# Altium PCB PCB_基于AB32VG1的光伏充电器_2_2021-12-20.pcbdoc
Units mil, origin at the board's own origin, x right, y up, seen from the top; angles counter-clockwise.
Board outline 4460 x 3310 mil, 2 copper layers (Top Layer, Bottom Layer); 86 components, 49 nets, 230 pads, 42 vias.
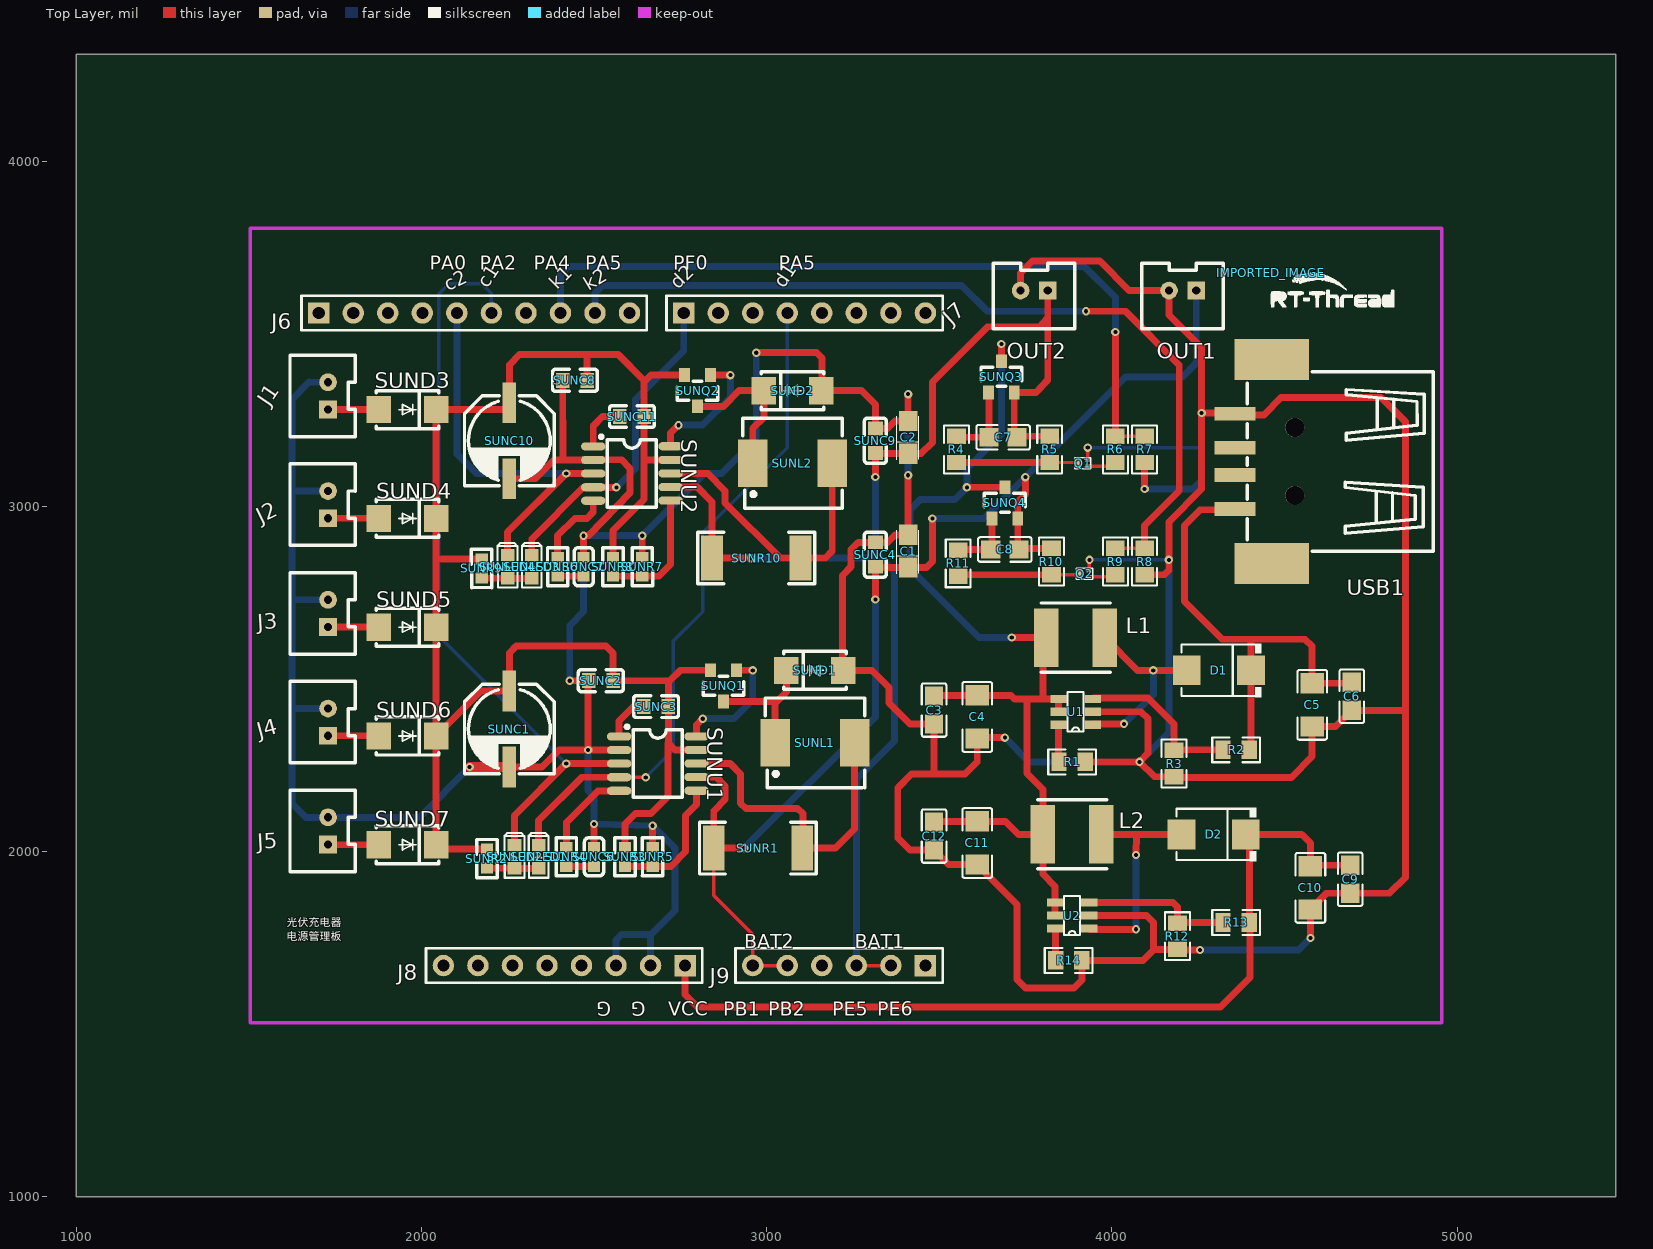
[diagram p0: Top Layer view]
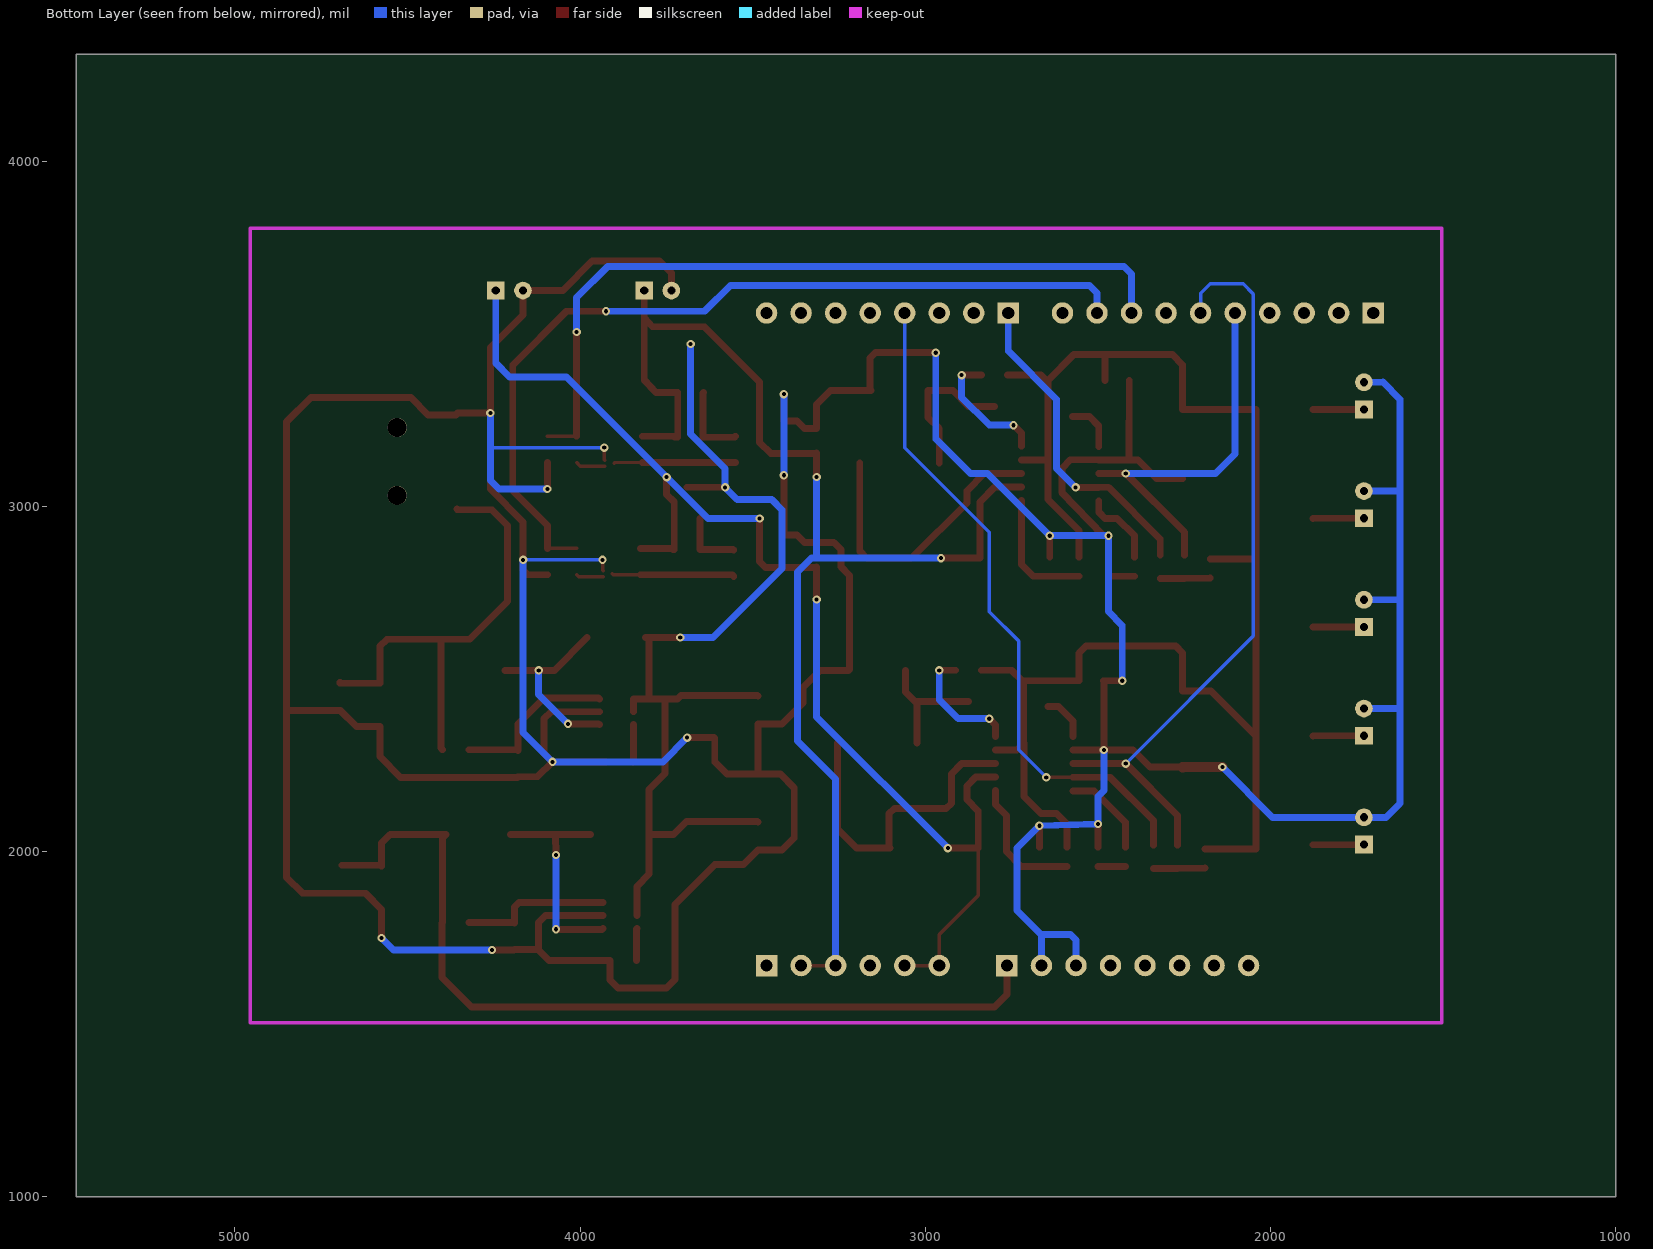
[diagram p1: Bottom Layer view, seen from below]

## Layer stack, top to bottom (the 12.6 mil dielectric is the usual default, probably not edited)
Top Layer: signal copper (thickness not stored)
Dielectric: dielectric 12.6, FR-4, Dk 4.8
Bottom Layer: signal copper (thickness not stored)

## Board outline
5460,1000 1000,1000 1000,4310 5460,4310

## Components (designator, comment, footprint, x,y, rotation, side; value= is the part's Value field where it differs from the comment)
C1 "10u" CASE-A_3216 3410,2870 r90 top
C2 "10u" CASE-A_3216 3410,3200 r90 top
C3 "0.1u" C0805 3485,2410 r90 top
C4 "22u" C1206 3610,2390 r90 top
C5 "22u" C1206 4580,2425 r90 top
C6 "0.1u" C0805 4695,2450 r90 top
C7 "0.1u" C0805 3685,3200 r180 top
C8 "0.1u" C0805 3690,2875 r180 top
C9 "0.1u" C0805 4690,1920 r90 top
C10 "22u" C1206 4575,1895 r90 top
C11 "22u" C1206 3610,2025 r90 top
C12 "0.1u" C0805 3485,2045 r90 top
D1 "SS34BG" SMB_L4.6-W3.6-LS5.3-RD 4310,2525 r180 top
D2 "SS34BG" SMB_L4.6-W3.6-LS5.3-RD 4295,2050 r180 top
IMPORTED_IMAGE "IMPORTED_IMAGE" IMPORTED_IMAGE 4460.66,3675.85 r0 top
J1 "XH2.0-2" XH2.0-2P 1730,3320 r180 top
J2 "XH2.0-2" XH2.0-2P 1730,3005 r180 top
J3 "XH2.0-2" XH2.0-2P 1730,2690 r180 top
J4 "XH2.0-2" XH2.0-2P 1730,2375 r180 top
J5 "XH2.0-2" XH2.0-2P 1730,2060 r180 top
J6 "HDR-M-2.54_1x10" HDR-M-2.54_1X10 2153,3560 r0 top
J7 "HDR-M-2.54_1x8" HDR-M-2.54_1X8 3160,3560 r0 top
J8 "HDR-M-2.54_1x8" HDR-M-2.54_1X8 2364,1670 r180 top
J9 "HDR-M-2.54_1x6" HDR-M-2.54_1X6 3210,1670 r180 top
L1 "3.3uH" IND-SMD_L5.0-W5.0_LQH55DN 3895,2620 r0 top
L2 "3.3uH" IND-SMD_L5.0-W5.0_LQH55DN 3885,2050 r0 top
OUT1 "XH2.0-2" XH2.0-2P 4205,3625 r270 top
OUT2 "XH2.0-2" XH2.0-2P 3775,3625 r270 top
Q1 "MMBT3904FN3" DFN-3L_L1.0-W0.6-P0.65-BR 3915,3125 r0 top
Q2 "MMBT3904FN3" DFN-3L_L1.0-W0.6-P0.65-BR 3920,2805 r0 top
R1 "47k" R0805 3885,2260 r180 top
R2 "88k" R0805 4360,2295 r0 top
R3 "12k" R0805 4180,2255 r90 top
R4 "100k" R0805 3550,3165 r90 top
R5 "10k" R0805 3820,3165 r90 top
R6 "10k" R0805 4010,3165 r270 top
R7 "100k" R0805 4095,3165 r90 top
R8 "100k" R0805 4095,2840 r90 top
R9 "10k" R0805 4010,2840 r270 top
R10 "10k" R0805 3825,2840 r90 top
R11 "100k" R0805 3555,2835 r90 top
R12 "12k" R0805 4190,1755 r90 top
R13 "88k" R0805 4360,1795 r0 top
R14 "47k" R0805 3875,1685 r180 top
SUNC1 "220uF" CAP-SMD_BD6.3-L6.6-W6.6-FD 2255,2355 r270 top
SUNC2 "0.1u" C0603#1 2520,2495 r0 top
SUNC3 "0.1u" C0603#1 2680,2420 r0 top
SUNC4 "0.1u" C0603#1 3315,2860 r270 top
SUNC6 "0.22uF" C0603#2 2500,1985 r270 top
SUNC7 "0.22uF" C0603#2 2470,2825 r270 top
SUNC8 "0.1u" C0603#1 2445,3365 r0 top
SUNC9 "0.1u" C0603#1 3315,3190 r270 top
SUNC10 "220uF" CAP-SMD_BD6.3-L6.6-W6.6-FD 2255,3190 r270 top
SUNC11 "0.1u" C0603#1 2610,3260 r0 top
SUND1 "SS54" SMA_L4.4-W2.8-LS5.4-R-RD 3140,2525 r0 top
SUND2 "SS54" SMA_L4.4-W2.8-LS5.4-R-RD 3075,3335 r0 top
SUND3 "SS54" SMA_L4.4-W2.8-LS5.4-R-RD 1960,3280 r180 top
SUND4 "SS54" SMA_L4.4-W2.8-LS5.4-R-RD 1960,2965 r180 top
SUND5 "SS54" SMA_L4.4-W2.8-LS5.4-R-RD 1960,2650 r180 top
SUND6 "SS54" SMA_L4.4-W2.8-LS5.4-R-RD 1960,2335 r180 top
SUND7 "SS54" SMA_L4.4-W2.8-LS5.4-R-RD 1960,2020 r180 top
SUNL1 "10uH" IND-SMD_L6.8-W6.8_SMMS0630 3140,2315 r0 top
SUNL2 "10uH" IND-SMD_L6.8-W6.8_SMMS0630 3075,3125 r0 top
SUNLED1 "G" LED0603_RED 2340,1985 r90 top
SUNLED2 "R" LED0603_RED 2270,1985 r90 top
SUNLED3 "G" LED0603_RED 2320,2825 r90 top
SUNLED4 "R" LED0603_RED 2250,2825 r90 top
SUNQ1 "AO3401A" SOT-23_L2.9-W1.3-P0.95-LS2.4-BR 2875,2480 r90 top
SUNQ2 "AO3401A" SOT-23_L2.9-W1.3-P0.95-LS2.4-BR 2800,3335 r90 top
SUNQ3 "AO3401A" SOT-23_L2.9-W1.3-P0.95-LS2.4-BR 3680,3375 r270 top
SUNQ4 "AO3401A" SOT-23_L2.9-W1.3-P0.95-LS2.4-BR 3690,3010 r270 top
SUNR1 "50mΩ" R2512 2975,2010 r180 top
SUNR2 "4.7k" R0603 2190,1980 r90 top
SUNR3 "33k" R0603 2590,1985 r90 top
SUNR4 "120R" R0603 2420,1985 r270 top
SUNR5 "10k" R0603 2670,1985 r270 top
SUNR6 "120R" R0603 2395,2825 r270 top
SUNR7 "10k" R0603 2640,2825 r270 top
SUNR8 "33k" R0603 2555,2825 r90 top
SUNR9 "4.7k" R0603 2175,2820 r90 top
SUNR10 "50mΩ" R2512 2970,2850 r180 top
SUNU1 "CN3791" SSOP-10_L4.9-W3.9-P1.00-LS6.0-BL 2685,2255 r270 top
SUNU2 "CN3791" SSOP-10_L4.9-W3.9-P1.00-LS6.0-BL 2610,3095 r270 top
U1 "PW5300" PW5300 3895,2405 r180 top
U2 "PW5300" PW5300 3885,1815 r180 top
USB1 "USB-TYPE A_Female" USB-A-SMD_USB-M-32 4410,3130 r90 top

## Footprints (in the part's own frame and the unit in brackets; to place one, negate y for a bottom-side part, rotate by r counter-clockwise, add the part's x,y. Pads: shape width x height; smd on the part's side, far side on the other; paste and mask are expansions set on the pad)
C0603#1 [mm]
  rect 1x1.1 smd: 1(-0.9,0) 2(0.9,0)
  silkscreen extent -1.65,-0.8 1.65,0.8
C0603#2 [mm]
  rect 0.8x0.9 smd: 1(-0.7,0) 2(0.7,0)
  silkscreen extent -1.4,-0.7 1.4,0.72
C0805 [mm]
  rect 1.41x1.35 smd: 1(-1.03,0) 2(1.03,0)
  silkscreen extent -1.96,-0.9 1.96,0.9
C1206 [mm]
  rect 1.485x1.728 smd: 1(-1.593,0) 2(1.593,0)
  silkscreen extent -2.56,-1.09 2.56,1.09
CAP-SMD_BD6.3-L6.6-W6.6-FD [mm]
  rect 3x1 smd: 1(-2.8,0) 2(2.8,0)
  silkscreen extent -3.3,-3.3 3.3,3.3
CASE-A_3216 [mil]
  rect 59.05x53.5 smd: 1(-47.24,0) 2(47.25,0)
  silkscreen extent -65,-30 61,33
DFN-3L_L1.0-W0.6-P0.65-BR [mm]
  rect 0.35x0.25 smd: 1(0.34,-0.22) 2(0.34,0.22)
  rect 0.35x0.6 smd: 3(-0.34,0)
  silkscreen extent -0.59,-0.4 0.61,0.4
HDR-M-2.54_1X6 [mil]
  rect 62x62 hole 35: 1(-250,0)
  round 62 hole 35: 2(-150,0) 3(-50,0) 4(50,0) 5(150,0) 6(250,0)
  silkscreen extent -300,-50 300,50
HDR-M-2.54_1X8 [mil]
  rect 62x62 hole 35: 1(-400,0)
  round 62 hole 35: 2(-300,0) 3(-200,0) 4(-100,0) 5(0,0) 6(100,0) 7(200,0) 8(300,0)
  silkscreen extent -450,-50 350,50
HDR-M-2.54_1X10 [mil]
  rect 62x62 hole 35: 1(-450,0)
  round 62 hole 35: 2(-350,0) 3(-250,0) 4(-150,0) 5(-50,0) 6(50,0) 7(150,0) 8(250,0) 9(350,0) 10(450,0)
  silkscreen extent -500,-50 500,50
IMPORTED_IMAGE [mil]
  silkscreen extent 0,-100 358,0
IND-SMD_L5.0-W5.0_LQH55DN [mm]
  rect 1.801x4.3 smd: 1(-2.15,0) 2(2.15,0)
  silkscreen extent -2.54,-2.54 2.54,2.54
IND-SMD_L6.8-W6.8_SMMS0630 [mm]
  rect 2.15x3.5 smd: 1(-2.925,0) 2(2.925,0)
  silkscreen extent -3.65,-3.3 3.65,3.3
LED0603_RED [mm]
  rect 0.9x1 smd: 1(-0.85,0) 2(0.85,0)
  silkscreen extent -1.54,-0.73 1.75,0.73
PW5300 [mm]
  rect 1.2x0.6 smd: 1(-1.25,0.95) 2(-1.25,0) 3(-1.25,-0.95) 4(1.25,-0.95) 5(1.25,0) 6(1.25,0.95)
  silkscreen extent -0.59,-1.45 0.59,1.45
R0603 [mm]
  rect 0.8x0.9 smd: 1(-0.7,0) 2(0.7,0)
  silkscreen extent -1.4,-0.75 1.4,0.76
R0805 [mil]
  rect 44.59x54.21 smd: 1(-38.04,0) 2(38.04,0)
  silkscreen extent -69,-36 69,36
R2512 [mm]
  rect 1.6x3.3 smd: 1(-3.25,0) 2(3.25,0)
  silkscreen extent -4.3,-1.9 4.3,1.9
SMA_L4.4-W2.8-LS5.4-R-RD [mm]
  rect 1.8x2 smd: 1(2.1,0) 2(-2.1,0)
  silkscreen extent -2.3,-1.4 2.3,1.4
SMB_L4.6-W3.6-LS5.3-RD [mil]
  rect 80.61x86.31 smd: 1(-92.94,0) 2(92.94,0)
  silkscreen extent -123,-77 108,77
SOT-23_L2.9-W1.3-P0.95-LS2.4-BR [mm]
  rect 1x0.8 smd: 1(1.15,-0.95) 2(1.15,0.95) 3(-1.15,0)
  silkscreen extent -0.7,-1.5 0.7,1.5
SSOP-10_L4.9-W3.9-P1.00-LS6.0-BL [mm]
  oval 0.6x1.8 smd: 1(-1.994,-2.845) 2(-0.996,-2.845) 3(0.005,-2.845) 4(1.006,-2.845) 5(2.004,-2.845) 6(1.994,2.845) 7(0.996,2.845) 8(-0.005,2.845) 9(-1.006,2.845) 10(-2.004,2.845)
  silkscreen extent -2.83,-2.38 2.48,1.8
USB-A-SMD_USB-M-32 [mm]
  rect 1x3 smd: 1(3.5,1.35) 2(1,1.35) 3(-1,1.35) 4(-3.5,1.35)
  rect 3x5.5 smd: 5(-7.5,-1.35) 6(7.5,-1.35)
  round 1.4 hole 1.4 unplated: ""(-2.5,-3.05) ""(2.5,-3.05)
  silkscreen extent -6.59,-13.21 6.61,0.46
XH2.0-2P [mm]
  rect 1.3x1.3 hole 0.6: 1(0,1)
  round 1.3 hole 0.6: 2(0,-1)
  silkscreen extent -2,-3 2.8,3

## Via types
v1: diameter 24, hole 12, Top Layer to Bottom Layer, 42 vias

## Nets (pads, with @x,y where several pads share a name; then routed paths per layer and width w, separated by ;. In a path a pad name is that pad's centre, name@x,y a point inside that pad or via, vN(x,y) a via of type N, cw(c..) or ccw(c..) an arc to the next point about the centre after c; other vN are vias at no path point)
BAT1: C2.1 C7.1 J9.2 J9.3 OUT2.1 R5.2 SUNC9.2 SUNQ3.2 SUNR10.2 SUNU2.7 | length 3885.7
  Top Layer w10: J9.3 J9.2
  Top Layer w20: SUNU2.7 2799.2,3055.8 2842.05,3012.95 2842.05,2850 v1(2955,2850) ; v1(3315,3085) SUNC9.2 3316.8,3152.76 C2.1 ; C2.1 3447.8,3152.8 3480,3185 3480,3360 3640,3520 3790,3520 3814.37,3545.63 OUT2.1 3814.37,3365.63 3779.72,3329.72 SUNQ3.2 3717.4,3200 C7.1 3728.59,3203.04 R5.2
  Bottom Layer w20: v1(2955,2850) 3330,2850 3370,2810 3370,2320 3260,2210 J9.3 ; v1(3315,3085) 3315.61,2850
BAT2: C1.1 C8.1 J9.5 J9.6 OUT1.1 R10.2 SUNC4.2 SUNQ4.2 SUNR1.2 SUNU1.7 | length 3610.2
  Top Layer w10: SUNR1.2@2847.05,2010 2847.05,1872.95 2960,1760 J9.6 J9.5
  Top Layer w20: SUNU1.7 2854.2,2215.8 2880,2190 2880,2150.9 2847.1,2117.9 SUNR1.2@2847.1,2010 ; SUNR1.2@2847.05,2010 v1(2935,2010) ; v1(3315,2730) SUNC4.2 3316.8,2822.76 C1.1 3462.76,2822.76 3480,2840 v1(3480,2965) ; v1(3749.49,3084.49) 3749.5,3034.5 3727.4,3012.4 SUNQ4.2 3727.4,2875 C8.1 3733.59,2878.04 R10.2
  Bottom Layer w20: v1(2935,2010) 3315,2390 v1(3315,2730) ; v1(3480,2965) 3630,2965 v1(3749.49,3084.49) 4040,3375 4205,3375 4244.4,3415.6 OUT1.1
C8_2: C8.2 R11.2 SUNQ4.1 | length 188.1
  Top Layer w20: R11.2 3556.96,2875 C8.2 3652.6,2875 SUNQ4.1
CHARGE1: J6.6 SUNLED2.2 SUNU1.3 | length 2199
  Top Layer w20: SUNLED2.2 2270,2105 v1(2419.79,2254.79) SUNU1.3
  Bottom Layer w10: J6.6 2203,3617 2175,3645 2080,3645 2050,3615 2050,2624.58 v1(2419.79,2254.79)
CHARGE2: J6.5 SUNLED4.2 SUNU2.3 | length 1133.4
  Top Layer w20: SUNLED4.2 2250,2925 v1(2419.8,3094.8) SUNU2.3
  Bottom Layer w20: J6.5 2103,3152 2160.2,3094.8 v1(2419.8,3094.8)
CTRL1: J6.8 R6.1 R7.2 | length 2253.4
  Top Layer w10: R6.1 R7.2
  Top Layer w20: R6.1 v1(4010,3505)
  Bottom Layer w20: J6.8 2403,3673 2425,3695 3920,3695 4010,3605 v1(4010,3505)
CTRL2: J6.9 R8.2 R9.1 | length 2512.8
  Top Layer w10: R9.1 R8.2
  Top Layer w20: v1(3925,3565) 4040,3565 4195,3410 4195,3045 4095,2945 R8.2
  Bottom Layer w20: J6.9 2503,3618 2525,3640 3565,3640 3640,3565 v1(3925,3565)
D2_2: D2.2 L2.2 U2.1 | length 644.3
  Top Layer w20: U2.1 3936.81,1775 v1(4070,1775) ; L2.2 D2.2 ; v1(4070,1990) 4070.76,2050
  Bottom Layer w20: v1(4070,1775) v1(4070,1990)
DONE1: J7.4 SUNLED1.2 SUNU1.4 | length 1948.3
  Top Layer w10: SUNU1.4 v1(2650,2215)
  Top Layer w20: SUNLED1.2 2340,2090 2465.39,2215.39 SUNU1.4
  Bottom Layer w10: v1(2650,2215) 2730,2295 2730,2610 2815,2695 2815,2925 3060,3170 J7.4
DONE2: J7.1 SUNLED3.2 SUNU2.4 | length 939.7
  Top Layer w20: SUNLED3.2 2320,2905 2470.4,3055.4 SUNU2.4 2498.4,3055 v1(2565,3055)
  Bottom Layer w20: v1(2565,3055) 2620,3110 2620,3310 2760,3450 J7.1
GND: C1.2 C2.2 C3.1 C4.1 C5.1 C6.1 C9.1 C10.1 C11.1 C12.1 J1.2 J2.2 J3.2 J4.2 J5.2 J8.2 J8.3 OUT1.2 OUT2.2 Q1.2 Q2.2 R1.1 R3.1 R7.1 R8.1 R12.1 R14.1 SUNC1.2 SUNC2.1 SUNC4.1 SUNC6.1 SUNC7.1 SUNC8.1 SUNC9.1 SUNC10.2 SUND1.1 SUND2.1 SUNR5.1 SUNR7.1 SUNU1.2 SUNU2.2 U1.2 U2.2 USB1.1 | length 18390.2
  Top Layer w10: Q1.2 3930,3135.27 v1(3930,3170) ; Q2.2 3935,2815.27 v1(3935,2845)
  Top Layer w20: SUNC1.2 2349.76,2244.76 2399.2,2294.2 SUNU1.2 ; SUNC10.2 2329.76,3079.76 2384.2,3134.2 SUNU2.2 2580,3135 2605,3110 2605,3040 2485,2915 v1(2470,2915) SUNC7.1 ; SUNC8.1 2410.39,3134.2 ; v1(2430,2495) SUNC2.1 2483.17,2493.6 v1(2483.17,2294.2) ; SUNC6.1 v1(2500,2080) ; SUNR7.1 v1(2640,2915) ; SUNR5.1 v1(2670,2075) ; v1(2970,3445) 3145,3445 3160,3430 3160,3337.32 SUND2.1 3275,3335 3315,3295 SUNC9.1 3350.43,3225.43 3372.25,3247.25 3410,3247.25 v1(3410,3325) ; v1(3410,3090) 3410,2917.25 3372.25,2917.25 3350.43,2895.43 SUNC4.1 3265.43,2895.43 3245,2875 3245,2825 3220,2800 3220,2527.68 SUND1.1 3305,2525 3355,2475 3355,2430 3415.55,2369.45 C3.1@3485,2369.45 ; 3485.41,2225 C3.1@3485.41,2369.45 ; v1(3690,2330) 3612.7,2330 C4.1 3610,2260 3575,2225 3420,2225 3380,2185 3380,2040 3415,2005 3485,2004.45 3527.15,1962.3 C11.1 3725,1847.3 3725,1630 3750,1605 3890,1605 3913.04,1628.04 R14.1 4090,1685 4121.96,1716.96 R12.1 ; OUT2.2 3735.63,3675.63 3770,3710 3965,3710 4050,3625 OUT1.2 4165.63,3554.37 4260,3460 v1(4260,3270) ; R1.1 v1(4080,2260) ; U2.2 4100,1815 4120,1795 4120,1716.96 R12.1 ; U1.2 4085,2405 4105,2385 4105,2285 v1(4080,2260) ; R8.1 4151.96,2801.96 4165,2815 4165,2955 4260,3050 v1(4260,3270) ; v1(4095,3050) R7.1 ; v1(4255,1715) 4191.96,1715 R12.1 ; USB1.1 4354.64,3270 v1(4260,3270) ; USB1.1 4359.6,3265 4440,3265 4490,3315 4780,3315 4850,3245 4850,1925 4804.4,1879.5 C9.1@4690,1879.5 ; v1(4575,1750) C10.1 4622.15,1879.45 C9.1@4690,1879.45 ; 4850,2408.44 4696.01,2408.44 C6.1 4647.85,2362.3 C5.1 4580,2275 4520,2215 4181.96,2215 R3.1 4123.04,2216.96 v1(4080,2260)
  Top Layer w30: v1(2140,2245) SUNC1.2
  Bottom Layer w10: v1(3930,3170) 4260,3170 4260,3164.73 ; v1(3935,2845) v1(4165,2845)
  Bottom Layer w20: 1625,2414.46 J4.2 ; 1625,2729.46 J3.2 ; 1625,3044.46 J2.2 ; J1.2 1675,3360 1625,3310 1625,2140 1665.63,2099.37 J5.2 1994.37,2099.37 v1(2140,2245) ; v1(2430,2495) 2430,2655 2470,2695 v1(2470,2915) v1(2640,2915) 2820,3095 2870,3095 2970,3195 v1(2970,3445) ; v1(2483.17,2294.2) 2483.17,2176.83 2500,2160 v1(2500,2080) v1(2670,2075) 2735,2010 2735,1830 2665,1760 2580,1760 2564,1744 J8.3 ; J8.2 2664.16,1760 ; v1(3410,3090) v1(3410,3325) ; v1(3690,2330) 3760,2260 v1(4080,2260) 4165,2345 v1(4165,2845) ; v1(4095,3050) 4235,3050 4260,3075 v1(4260,3270) ; v1(4255,1715) 4540,1715 v1(4575,1750)
J1_1: J1.1 SUND3.1 | length 147.3
  Top Layer w20: J1.1 SUND3.1
J2_1: J2.1 SUND4.1 | length 147.3
  Top Layer w20: J2.1 SUND4.1
J3_1: J3.1 SUND5.1 | length 147.3
  Top Layer w20: J3.1 SUND5.1
J4_1: J4.1 SUND6.1 | length 147.3
  Top Layer w20: J4.1 SUND6.1
J5_1: J5.1 SUND7.1 | length 147.3
  Top Layer w20: J5.1 SUND7.1
POWER: SUNC1.1 SUNC2.2 SUNC3.2 SUNC8.2 SUNC10.1 SUNC11.2 SUND3.2 SUND4.2 SUND5.2 SUND6.2 SUND7.2 SUNQ1.2 SUNQ2.2 SUNR2.2 SUNR3.2 SUNR8.2 SUNR9.2 SUNU1.9 SUNU2.9 | length 4882.7
  Top Layer w20: 2042.68,2847.56 SUNR9.2 ; SUNR2.2 2042.7,2007.6 SUND7.2 SUND6.2 ; SUNC10.1 2255,3280 SUND3.2 SUND4.2 SUND5.2 SUND6.2 ; SUNC10.1 2255,3410 2284.56,3439.56 2480.44,3439.56 ; SUNC8.2 2480.44,3439.56 ; SUNR8.2 2555,2930 2645.4,3020.4 2645.4,3149.6 ; SUNR3.2 2590,2080 2620,2110 2665,2110 2715,2160 2715,2314.56 ; SUNC11.2 2645.4,3360.4 2665.3,3380.3 SUNQ2.2 ; 2645.4,3364.6 2570.44,3439.56 2480.44,3439.56 ; SUNC11.2 2645.44,3134.6 SUNU2.9 ; 2715.44,2495 SUNC3.2 2715.44,2314.56 2735.41,2294.59 SUNU1.9 ; SUNQ1.2 2750.28,2525.28 2720,2495 SUNC2.2 2555.44,2574.56 2535,2595 2275,2595 2255,2575 SUNC1.1 2172.92,2465.24 SUND6.2
Q1_1: Q1.1 R6.2 | length 86
  Top Layer w10: Q1.1 3999.37,3116.33 R6.2
Q1_3: Q1.3 R4.1 R5.1 | length 352.4
  Top Layer w10: R5.1 3899.65,3126.96 Q1.3
  Top Layer w20: R4.1 R5.1
R9_2: Q2.1 R9.2 | length 78.9
  Top Layer w10: Q2.1 4004.37,2796.33 R9.2
R10_1: Q2.3 R10.1 R11.1 | length 354.9
  Top Layer w10: R10.1 3903.57,2801.96 Q2.3
  Top Layer w20: R11.1 3560,2801.96 R10.1
R12_2: R12.2 R13.1 U2.3 | length 440.7
  Top Layer w20: U2.3 4177.6,1852.4 4190,1840 R12.2 4191.96,1795 R13.1
R14_2: R14.2 U2.6 | length 93.1
  Top Layer w20: U2.6 3836.96,1776.43 R14.2
S$68: 
SUNC3_1: SUNC3.1 SUNU1.1 | length 133.5
  Top Layer w20: SUNU1.1 2573,2378 2615,2420 SUNC3.1
SUNC7_2: SUNC7.2 SUNR6.2 | length 75
  Top Layer w20: SUNR6.2 SUNC7.2
SUND2_2: SUND2.2 SUNL2.1 SUNQ2.3 | length 434.5
  Top Layer w20: SUNQ2.3 2874.72,3289.72 2920,3335 SUND2.2 2992.3,3257.3 2959.8,3224.8 SUNL2.1
SUNL1_2: SUNL1.2 SUNR1.1 SUNU1.8 | length 944.8
  Top Layer w20: SUNU1.8 2894.8,2255.2 2925,2225 2925,2140 2940,2125 3090,2125 3105,2110 3105,2010 SUNR1.1 ; SUNR1.1 3200,2010 3255.16,2065.16 SUNL1.2
SUNLED2_1: SUNLED1.1 SUNLED2.1 SUNR2.1 | length 150
  Top Layer w20: SUNR2.1 SUNLED2.1 ; SUNLED2.1 SUNLED1.1
SUNQ1_1: SUNQ1.1 SUNU1.10 | length 358.9
  Top Layer w20: SUNU1.10 2797,2367 v1(2815,2385) ; SUNQ1.1 v1(2960,2525)
  Bottom Layer w20: v1(2815,2385) 2905,2385 2960,2440 v1(2960,2525)
SUNQ1_3: SUND1.2 SUNL1.1 SUNQ1.3 | length 376.1
  Top Layer w20: SUNQ1.3 3029.7,2434.7 3057.3,2462.3 SUND1.2 ; SUNL1.1 3024.84,2434.7
SUNQ3_1: C7.2 R4.2 SUNQ3.1 | length 226.2
  Top Layer w20: R4.2 3553.04,3200 C7.2 3644.45,3327.87 SUNQ3.1
SUNR4_2: SUNC6.2 SUNR4.2 | length 80
  Top Layer w20: SUNR4.2 SUNC6.2
SUNR6_1: SUNR6.1 SUNU2.5 | length 226.7
  Top Layer w20: SUNR6.1 2395,2915 2445,2965 2480,2965 2498,2983 SUNU2.5
SUNR7_2: SUNR7.2 SUNR8.1 SUNU2.6 | length 365.9
  Top Layer w20: SUNR8.1 SUNR7.2 ; SUNR7.2 2687.6,2797.4 2722,2831.9 SUNU2.6
SUNR9_1: SUNLED3.1 SUNLED4.1 SUNR9.1 | length 145
  Top Layer w20: SUNR9.1 SUNLED4.1 ; SUNLED4.1 SUNLED3.1
SUNR10_1: SUNL2.2 SUNR10.1 SUNU2.8 | length 853.3
  Top Layer w20: SUNU2.8 2830,3095 2880,3045 2880,3010 3040,2850 SUNR10.1 3170,2850 3190.16,2870.16 SUNL2.2
SUNU1_5: SUNR4.1 SUNU1.5 | length 263.2
  Top Layer w20: SUNR4.1 2420,2085 2511.09,2176.09 SUNU1.5
SUNU1_6: SUNR3.1 SUNR5.2 SUNU1.6 | length 382.5
  Top Layer w20: SUNR3.1 SUNR5.2 ; SUNR5.2 2722.6,1957.4 2765,1999.9 2765,2105 2797,2137 SUNU1.6
SUNU2_1: SUNC11.1 SUNU2.1 | length 147.3
  Top Layer w20: SUNU2.1 2498,3233 2525,3260 SUNC11.1
SUNU2_10: SUNQ2.1 SUNU2.10 | length 376.4
  Top Layer w20: SUNU2.10 2722,3212 v1(2745,3235) ; SUNQ2.1 v1(2895,3380)
  Bottom Layer w20: v1(2745,3235) 2815,3235 2895,3315 v1(2895,3380)
U1_1: D1.2 L1.2 U1.1 | length 558.8
  Top Layer w20: U1.1 3946.61,2370 v1(4035,2370) ; L1.2 4074.64,2525 v1(4120,2525) D1.2
  Bottom Layer w20: v1(4035,2370) 4120,2455 v1(4120,2525)
U1_3: R2.1 R3.2 U1.3 | length 487.7
  Top Layer w20: U1.3 3946.81,2445 4105,2445 4180,2370 R3.2 4181.96,2295 R2.1
U1_6: R1.2 U1.6 | length 108.8
  Top Layer w20: U1.6 3845.8,2260 R1.2
USB1_2: USB1.2
USB1_3: USB1.3
VDD: C3.2 C4.2 C11.2 C12.2 L1.1 L2.1 SUNQ3.3 SUNQ4.3 U1.4 U1.5 U2.4 U2.5 | length 3030.3
  Top Layer w20: C12.2@3485,2085.55 3487.15,2087.7 C11.2 3692.3,2087.7 3730,2050 L2.1 ; C3.2@3485,2450.55 3487.15,2452.7 C4.2 3707.3,2452.7 3717.6,2442.4 U1.4 U1.5 ; v1(3580,3055) SUNQ4.3 ; SUNQ3.3 v1(3680,3470) ; v1(3710,2620) L1.1 ; 3754.06,2442.4 3754.06,2225.95 3800.36,2179.64 L2.1 ; 3800,2442.4 L1.1@3800,2620 ; U2.5 U2.4 3835.79,1899.21 3800.36,1934.64 L2.1
  Bottom Layer w20: v1(3680,3470) 3680,3210 3580,3110 v1(3580,3055) 3545,3020 3445,3020 3415,2990 3415,2820 3615,2620 v1(3710,2620)
VMCU: C9.2 C10.2 D2.1 J8.1 R13.2 | length 2571
  Top Layer w20: J8.1 2764,1586 2800,1550 4315,1550 4400,1635 4400,1793.04 R13.2 4398.04,2039.9 D2.1 4550,2050 4575,2025 C10.2 4577.85,1960.55 C9.2@4690,1960.55
VOUT: C5.2 C6.2 D1.1 R2.2 USB1.4 | length 1379.5
  Top Layer w20: USB1.4 4354.65,2990 4255,2990 4210,2945 4210,2725 4320,2615 4425,2615 ; R2.2 4402.94,2299.9 D1.1 4402.94,2615 4560,2615 4580,2595 C5.2 4695,2487.7 C6.2@4695,2490.55
pads on no net: J6.1 J6.2 J6.3 J6.4 J6.7 J6.10 J7.2 J7.3 J7.5 J7.6 J7.7 J7.8 J8.4 J8.5 J8.6 J8.7 J8.8 J9.1 J9.4 USB1. USB1.5 USB1.6

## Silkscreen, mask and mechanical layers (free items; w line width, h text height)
Top Overlay:
  text "PA0" at 2025,3685 h40
  text "PA2" at 2170,3685 h40
  text "PA4" at 2325,3685 h40
  text "PA5" at 2475,3685 h40
  text "PF0" at 2730,3685 h40
  text "PA5" at 3035,3685 h40
  text "c1" at 2191.77,3629.11 h40 r57
  text "d1" at 3051.77,3629.11 h40 r57
  text "k1" at 2394.14,3625.86 h40 r45
  text "d2" at 2744.14,3625.86 h40 r45
  text "k2" at 2485.3,3622.86 h40 r31
  text "c2" at 2078.77,3622.02 h40 r26
  text "光伏充电器 / 电源管理板" at 1610,1735 h40
  text "BAT2" at 2935,1720 h40
  text "BAT1" at 3255,1720 h40
  text "G" at 2550,1565 h40 r180
  text "G" at 2650,1565 h40 r180
  text "VCC" at 2715,1525 h40
  text "PB1" at 2875,1525 h40
  text "PB2" at 3005,1525 h40
  text "PE5" at 3190,1525 h40
  text "PE6" at 3320,1525 h40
